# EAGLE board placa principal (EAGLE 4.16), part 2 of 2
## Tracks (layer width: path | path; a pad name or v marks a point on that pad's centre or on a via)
A0
  Bottom 0.305: 18-A0.1 45.71,10.27 arc45 45.34,11.17 39.1,17.41 arc-45 38.73,18.31 38.73,22.23 33.84,38.13 arc73 U2.2 RN3.2
A1
  Top 0.305: U2.17 37.99,33.66 arc-45 37.09,34.03 36.56,34.55 arc45 35.66,34.92 32.27,34.92 arc-45 31.37,35.3 RN3.3
  Bottom 0.305: 17-A1.1 44.82,3.44 arc-45 44.45,4.34 44.45,10.27 arc45 44.07,11.17 38.47,16.77 arc-45 38.09,17.67 38.09,21.91 34.25,34.04 arc72 33.04,34.92 32.27,34.92 arc-45 31.37,35.3 RN3.3
A1''
  Top 0.305: U8.4 131.55,48.26 arc-45 132.45,47.89 133.34,46.99 139.06,46.99 139.32,47.25 arc-45 140.22,47.62 144.78,47.62 X1.23
A2
  Bottom 0.305: 16-A2.1 43.17,10.27 arc45 42.8,11.17 37.83,16.14 arc-45 37.46,17.04 37.46,21.27 33.84,33.05 arc73 U2.4 RN3.4
A3
  Top 0.305: U2.15 37.99,28.57 arc-45 37.09,28.95 36.56,29.47 arc45 35.66,29.84 32.27,29.84 arc-45 31.37,30.22 RN3.5
  Bottom 0.305: 15-A3.1 42.28,3.44 arc-45 41.9,4.34 41.9,10.27 arc45 41.53,11.17 37.2,15.5 arc-45 36.82,16.4 36.82,20.45 arc17 36.77,20.82 34.24,28.95 arc73 33.03,29.84 32.27,29.84 arc-45 31.37,30.22 RN3.5
A4
  Bottom 0.305: 14-A4.1 40.63,10.27 arc45 40.26,11.17 36.56,14.87 arc-45 36.19,15.77 36.19,20.13 arc17 36.13,20.5 33.65,28.57 U2.6 RN3.6
A5
  Top 0.305: RN3.7 31.37,25.14 arc45 32.27,24.77 35.66,24.77 arc-45 36.56,24.39 37.09,23.87 arc45 37.99,23.5 U2.13
  Bottom 0.305: 13-A5.1 39.74,3.44 arc-45 39.36,4.34 39.36,10.27 arc45 38.99,11.17 35.93,14.23 arc-45 35.55,15.13 35.55,19.8 arc18 35.49,20.2 34.26,23.9 arc72 33.05,24.77 32.27,24.77 arc-45 31.37,25.14 RN3.7
A6
  Bottom 0.305: 12-A6.1 38.09,10.27 arc45 37.72,11.17 35.29,13.6 arc-45 34.92,14.5 34.92,19.18 arc17 34.86,19.55 33.84,22.89 arc73 U2.8 RN3.8
A7
  Top 0.305: U2.11 37.99,18.41 arc-45 37.09,18.79 36.56,19.31 arc45 35.66,19.68 32.27,19.68 arc-45 31.37,20.06 RN3.9
  Bottom 0.305: 11-A7.1 37.2,3.44 arc-45 36.82,4.34 36.82,10.27 arc45 36.45,11.17 32.12,15.5 arc-45 31.75,16.4 31.75,19.16 arc45 31.37,20.06 RN3.9
A8
  Bottom 0.305: 10-A8.1 35.55,9.63 arc45 35.18,10.53 30.21,15.5 arc45 29.31,15.88 26.56,15.88 arc-45 25.66,16.25 23.86,18.04 arc-45 23.49,18.94 23.49,22.03 arc17 23.43,22.41 18.41,38.73 U1.2 RN1.2
A9
  Top 0.305: RN1.3 16.13,35.3 arc45 17.03,34.92 19.79,34.92 arc-45 20.69,34.55 21.21,34.03 arc45 22.11,33.66 U1.17
  Bottom 0.305: RN1.3 16.13,35.3 arc45 17.03,34.92 17.8,34.92 arc-72 19.01,34.04 22.86,21.91 22.86,18.31 arc45 23.23,17.41 25.02,15.61 arc45 25.92,15.24 28.68,15.24 arc-45 29.58,14.87 33.91,10.53 arc-45 34.28,9.63 34.28,4.34 arc45 34.66,3.44 9-A9.1
A10
  Bottom 0.305: 8-A10.1 33.02,9.63 arc45 32.64,10.53 28.94,14.23 arc45 28.04,14.61 25.29,14.61 arc-45 24.39,14.98 22.59,16.77 arc-45 22.22,17.67 22.22,21.27 18.6,33.05 arc73 U1.4 RN1.4
A11
  Top 0.305: RN1.5 16.13,30.22 arc45 17.03,29.84 20.42,29.84 arc-45 21.32,29.47 21.85,28.95 arc45 22.75,28.57 U1.15
  Bottom 0.305: RN1.5 16.13,30.22 arc45 17.03,29.84 17.79,29.84 arc-73 19.01,28.95 21.59,20.64 21.59,17.04 arc45 21.96,16.14 23.75,14.34 arc45 24.65,13.97 27.41,13.97 arc-45 28.31,13.6 31.37,10.53 arc-45 31.75,9.63 31.75,4.34 arc45 32.12,3.44 7-A11.1
A12
  Bottom 0.305: 6-A12.1 30.48,9.63 arc45 30.1,10.53 27.67,12.96 arc45 26.77,13.34 24.02,13.34 arc-45 23.12,13.71 21.32,15.5 arc-45 20.95,16.4 20.95,20.32 18.6,27.97 arc73 U1.6 RN1.6
A13
  Top 0.305: RN1.7 16.13,25.14 arc45 17.03,24.77 19.79,24.77 arc-45 20.69,24.39 21.21,23.87 arc45 22.11,23.5 U1.13
  Bottom 0.305: RN1.7 16.13,25.14 arc45 17.03,24.77 17.81,24.77 arc-72 19.02,23.9 20.32,20 20.32,15.77 arc45 20.69,14.87 22.48,13.07 arc45 23.38,12.7 26.14,12.7 arc-45 27.04,12.33 28.83,10.53 arc-45 29.21,9.63 29.21,4.34 arc45 29.58,3.44 5-A13.1
A14
  Bottom 0.305: 4-A14.1 27.94,9.63 arc45 27.56,10.53 26.4,11.69 arc45 25.5,12.06 22.75,12.06 arc-45 21.85,12.44 20.05,14.23 arc-45 19.68,15.13 19.68,19.37 18.6,22.89 arc73 U1.8 RN1.8
A15
  Top 0.305: RN1.9 16.13,20.06 arc45 17.03,19.68 20.42,19.68 arc-45 21.32,19.31 21.85,18.79 arc45 22.75,18.41 U1.11
  Bottom 0.305: RN1.9 16.13,20.06 arc-45 16.51,19.16 16.51,17.04 arc45 16.88,16.14 21.21,11.8 arc45 22.11,11.43 24.87,11.43 arc-45 25.77,11.06 26.29,10.53 arc-45 26.67,9.63 26.67,4.34 arc45 27.04,3.44 3-A15.1
A'0  (via drill 0.8)
  Top 0.254: 112.39,52.39 131.44,52.39
  Top 0.305: U2.18 RN4.2 | U12.10 111.76,76.2 110.86,75.3 arc-45 109.96,74.93 109.74,74.93 arc45 108.84,74.56 107.68,73.4 arc-45 106.78,73.03 50.69,73.03 arc-45 49.79,73.4 v46.98,76.2 | 131.44,52.39 131.7,52.12 arc-45 132.08,51.23 132.08,50.06 arc45 132.45,49.16 132.97,48.63 arc45 133.87,48.26 U8.11 | v111.12,53.34 arc-45 111.66,53.12 112.39,52.39
  Bottom 0.305: RN4.2 44.07,39.63 arc45 44.45,40.53 44.45,50.91 arc-45 44.82,51.81 45.34,52.33 arc45 45.71,53.23 45.71,63.61 arc-45 46.09,64.51 46.61,65.03 arc45 46.98,65.93 v46.98,76.2 46.98,80.64 | v111.12,53.34 111.38,53.6 arc45 111.76,54.5 111.76,55.99 arc-45 112.13,56.89 112.65,57.41 arc45 113.03,58.31 113.03,74.4 arc45 112.65,75.3 112.13,75.83 arc-45 111.76,76.73 U12.10
  Bottom 1.27: 46.98,80.64 46.98,87.63
A'1  (via drill 0.8)
  Top 0.254: 117.79,49.85 124.77,49.85
  Top 0.305: U2.3 35.98,36.2 arc-45 36.88,35.82 37.4,35.3 arc45 38.3,34.92 41.38,34.92 arc45 42.28,35.3 RN4.3 | 46.98,80.64 46.98,80.01 v45.71,78.74 45.71,76.09 arc45 46.09,75.19 48.52,72.76 arc45 49.42,72.39 107.42,72.39 arc45 108.32,72.76 109.48,73.92 arc-45 110.38,74.3 111.86,74.3 arc45 112.76,74.67 114.3,76.2 U12.9 | 124.77,49.85 125.35,50.43 arc-45 126.25,50.8 U8.3 | v116.84,50.8 117.79,49.85
  Top 1.27: 46.98,80.64 46.98,87.63
  Bottom 0.305: RN4.3 43.07,36.2 arc-45 42.17,36.57 arc-45 41.9,37.2 41.9,50.27 arc-45 42.28,51.17 44.71,53.6 arc45 45.08,54.5 45.08,64.24 arc-45 45.45,65.14 arc45 45.71,65.78 v45.71,78.74 | U12.9 114.3,76.73 arc45 114.67,75.83 115.19,75.3 arc-45 115.56,74.4 115.56,52.6 arc45 115.94,51.7 v116.84,50.8
A'2  (via drill 0.8)
  Top 0.305: U2.16 RN4.4 | U12.8 116.84,76.2 113.4,72.76 arc-45 112.5,72.39 v109.85,72.39 109.59,72.13 arc-45 108.69,71.75 48.15,71.75 arc-45 47.25,72.13 44.82,74.56 arc-45 44.45,75.46 v44.45,76.2
  Bottom 0.305: RN4.4 42.54,33.66 41.64,34.55 arc45 40.74,34.92 40.6,34.92 arc-72 39.39,35.79 39.36,35.88 39.36,49.64 arc-45 39.74,50.54 44.07,54.87 arc45 44.45,55.77 v44.45,76.2 44.45,81.28 | U10.1 100.7,56.78 arc-45 100.33,57.68 100.33,62.34 arc-45 100.7,63.24 v109.85,72.39
  Bottom 1.27: 44.45,80.64 44.45,81.28 44.45,87.63
A'3  (via drill 0.8)
  Top 0.305: RN4.5 41.9,29.84 37.99,29.84 arc-45 37.09,30.22 36.56,30.74 arc45 35.66,31.11 U2.5 | 44.45,80.64 44.45,80.01 v43.17,78.74 43.17,75.46 arc45 43.55,74.56 46.61,71.49 arc45 47.51,71.12 113.77,71.12 arc45 114.67,71.49 119.38,76.2 U12.7
  Top 1.27: 44.45,80.64 44.45,87.63
  Bottom 0.305: v43.17,78.74 43.17,56.41 arc-45 42.8,55.51 37.83,50.54 arc45 37.46,49.64 37.46,39.37 39.4,33.27 arc72 40.61,32.38 40.74,32.38 arc-45 41.64,32.01 42.54,31.11 RN4.5 | U9.4 116.63,48.26 arc45 117.52,48.63 117.73,48.84 arc45 118.11,49.74 118.11,74.4 arc-45 118.48,75.3 119,75.83 arc45 119.38,76.73 U12.7
A'4  (via drill 0.8)
  Top 0.305: U2.14 RN4.6 | U12.6 121.92,76.2 116.57,70.86 arc-45 115.67,70.48 46.88,70.48 arc-45 45.98,70.86 42.28,74.56 arc-45 41.9,75.46 v41.9,76.2
  Bottom 0.305: RN4.6 42.54,28.57 41.64,29.47 arc45 40.74,29.84 40.61,29.84 arc-72 39.4,30.73 36.82,38.73 36.82,50.91 arc-45 37.2,51.81 41.53,56.14 arc45 41.9,57.04 v41.9,76.2 41.9,80.64 | U9.5 117.58,45.72 arc45 118.48,46.09 arc45 118.74,46.73 118.74,57.89 arc-45 119.11,58.79 120.65,60.33 120.65,74.4 arc-45 121.02,75.3 121.54,75.83 arc45 121.92,76.73 U12.6
  Bottom 1.27: 41.9,80.64 41.9,87.63
A'5  (via drill 0.8)
  Top 0.254: 112.07,54.29 107.95,54.29
  Top 0.305: RN4.7 42.54,26.04 41.27,24.77 37.99,24.77 arc-45 37.09,25.14 36.56,25.66 arc45 35.66,26.04 U2.7 | 41.9,80.64 41.9,80.01 v40.63,78.74 40.63,75.46 arc45 41.01,74.56 45.34,70.22 arc45 46.24,69.85 117.58,69.85 arc45 118.48,70.22 124.45,76.2 U12.5 | 107.95,54.29 107.37,53.71 arc-45 106.47,53.34 U10.2 | 112.07,54.29 arc-45 112.84,54.61 127.89,54.61 arc45 128.53,54.87 arc45 128.9,55.77 v128.9,55.88
  Top 1.27: 41.9,80.64 41.9,87.63
  Bottom 0.305: v40.63,78.74 40.63,57.68 arc-45 40.26,56.78 36.56,53.08 arc45 36.19,52.18 36.19,38.1 39.4,28.18 arc72 40.61,27.3 40.74,27.3 arc-45 41.64,26.93 42.54,26.04 RN4.7 | U12.5 125.35,75.94 arc-45 125.73,75.04 125.73,60.22 arc45 126.1,59.32 128.9,56.52 v128.9,55.88
A'6  (via drill 0.8)
  Top 0.254: 125.41,49.21 115.56,49.21 | 114.93,49.85 105.72,49.85
  Top 0.305: U2.12 RN4.8 | U12.4 127,76.2 120.38,69.59 arc-45 119.48,69.22 45.61,69.22 arc-45 44.71,69.59 39.74,74.56 arc-45 39.36,75.46 v39.36,76.2 | 105.72,49.85 105.14,50.43 arc45 104.24,50.8 U10.3 | v129.53,49.53 126.17,49.53 arc45 125.41,49.21 | 115.56,49.21 114.93,49.85
  Bottom 0.305: 39.36,80.64 v39.36,76.2 39.36,58.31 arc-45 38.99,57.41 35.93,54.35 arc45 35.55,53.45 35.55,37.15 39.39,25.63 arc72 40.6,24.77 40.74,24.77 arc-45 41.64,24.39 42.54,23.5 RN4.8 | U12.4 127.89,75.94 arc-45 128.27,75.04 128.27,58.95 arc45 128.64,58.05 129.8,56.89 arc-45 130.17,55.99 130.17,55.77 arc-45 129.8,54.87 129.53,54.61 v129.53,49.53
  Bottom 1.27: 39.36,80.64 39.36,87.63
A'7  (via drill 0.8)
  Top 0.305: RN4.9 42.28,20.06 arc-45 41.38,19.68 37.99,19.68 arc-45 37.09,20.06 36.56,20.58 arc45 35.66,20.95 U2.9 | 39.36,80.64 39.36,80.01 v38.09,78.74 38.09,75.46 arc45 38.47,74.56 44.07,68.95 arc45 44.97,68.58 121.39,68.58 arc45 122.29,68.95 129.53,76.2 U12.3 | v34.92,55.24 38.2,55.24 arc-45 39.1,54.87 44.07,49.9 arc45 44.97,49.53 77.57,49.53 arc-45 78.47,49.16 86.62,41.01 arc45 87.52,40.64 U11.9
  Top 1.27: 39.36,80.64 39.36,87.63
  Bottom 0.305: RN4.9 42.54,20.95 41.64,21.85 arc45 40.74,22.23 40.6,22.23 arc-72 39.4,23.1 34.98,36.64 arc-18 34.92,37.03 v34.92,55.24 37.72,58.05 arc45 38.09,58.95 v38.09,78.74
A'8  (via drill 0.8)
  Top 0.305: U1.18 RN2.2 | U12.25 127,61.7 arc45 126.62,62.6 121.65,67.57 arc45 120.75,67.94 44.34,67.94 arc-45 43.44,68.32 37.2,74.56 arc-45 36.82,75.46 v36.82,76.2 | v33.65,56.52 38.2,56.52 arc-45 39.1,56.14 44.71,50.54 arc45 45.61,50.16 77.89,50.16 arc-45 78.79,49.79 85.03,43.55 arc45 85.93,43.18 U11.8
  Bottom 0.305: RN2.2 28.83,39.63 arc45 29.21,40.53 29.21,51.54 arc-45 29.58,52.44 v33.65,56.52 36.45,59.32 arc45 36.82,60.22 v36.82,76.2 36.82,80.64
  Bottom 1.27: 36.82,80.64 36.82,87.63
A'9  (via drill 0.8)
  Top 0.305: RN2.3 27.04,35.3 arc-45 26.14,34.92 22.11,34.92 arc-45 21.21,35.3 20.69,35.82 arc45 19.79,36.2 U1.3 | 36.82,80.64 36.82,80.01 v35.55,78.74 35.55,75.46 arc45 35.93,74.56 42.8,67.68 arc45 43.7,67.31 118.85,67.31 arc-45 119.75,66.94 124.08,62.6 arc-45 124.45,61.7 U12.24 | v118.11,43.18 117.21,42.28 arc-45 116.31,41.91 113.55,41.91 arc45 112.65,41.54 110.48,39.37 107.2,39.37 arc-45 106.3,39.74 103.24,42.81 arc45 102.34,43.18 U10.6
  Top 1.27: 36.82,80.64 36.82,87.63
  Bottom 0.305: RN2.3 27.04,37.09 arc-45 26.67,37.99 26.67,50.91 arc-45 27.04,51.81 35.18,59.95 arc45 35.55,60.85 v35.55,78.74 | U12.24 124.45,60.96 119.75,56.25 arc45 119.38,55.35 119.38,44.98 arc-45 119,44.08 v118.11,43.18
A'10  (via drill 0.8)
  Top 0.305: U1.16 RN2.4 | v116.84,64.14 114.67,66.3 arc45 113.77,66.67 43.07,66.67 arc-45 42.17,67.05 34.66,74.56 arc-45 34.28,75.46 v34.28,76.2 | U11.7 88.79,45.72 arc-45 87.89,46.09 87.36,46.62 arc45 86.46,46.99 84.34,46.99 arc-45 83.44,47.36 79.74,51.06 arc45 78.84,51.44 66.56,51.44 arc-45 65.66,51.81 63.87,53.6 arc45 62.97,53.98 43.07,53.98 arc-45 42.17,54.35 39.1,57.41 arc45 38.2,57.78 v31.11,57.78
  Bottom 0.305: RN2.4 27.04,34.55 arc45 26.14,34.92 25.44,34.92 arc-56 24.38,35.49 24.34,35.56 arc-34 24.12,36.26 24.12,50.27 arc-45 24.5,51.17 v31.11,57.78 33.91,60.59 arc45 34.28,61.49 v34.28,76.2 34.28,80.64 | v116.84,64.14 U12.21
  Bottom 1.27: 34.28,80.64 34.28,87.63
A'11  (via drill 0.8)
  Top 0.305: RN2.5 26.67,29.84 22.75,29.84 arc-45 21.85,30.22 21.32,30.74 arc45 20.42,31.11 U1.5 | 34.28,80.64 34.28,80.01 v33.02,78.74 33.02,75.46 arc45 33.39,74.56 41.53,66.41 arc45 42.43,66.04 108.69,66.04 arc-45 109.59,65.67 112.02,63.24 arc45 112.92,62.87 120.91,62.87 arc-45 121.54,62.6 arc-45 121.92,61.7 U12.23 | v30.48,59.05 38.2,59.05 arc-45 39.1,58.68 42.8,54.98 arc45 43.7,54.61 76.3,54.61 arc-45 77.2,54.24 77.73,53.71 arc45 78.63,53.34 79.48,53.34 arc-45 80.38,52.97 84.71,48.63 arc45 85.61,48.26 U11.6
  Top 1.27: 34.28,80.64 34.28,87.63
  Bottom 0.305: RN2.5 27.04,32.01 arc45 26.14,32.38 25.32,32.38 arc-69 24.13,33.21 23.57,34.71 arc-21 23.49,35.16 23.49,51.54 arc-45 23.86,52.44 v30.48,59.05 33.02,61.59 v33.02,78.74
A'12  (via drill 0.8)
  Top 0.254: 100.01,49.21 103.18,49.21
  Top 0.305: U1.14 RN2.6 | v29.84,60.33 38.2,60.33 arc-45 39.1,59.95 43.44,55.62 arc45 44.34,55.24 71.22,55.24 arc45 72.12,55.62 arc-45 72.76,55.88 79.48,55.88 arc-45 80.38,55.51 84.71,51.17 arc45 85.61,50.8 U11.5 89.64,50.8 arc-45 90.54,50.43 93.6,47.36 arc45 94.5,46.99 97.26,46.99 arc45 98.16,47.36 100.01,49.21 | 103.18,49.21 105.03,47.36 arc45 105.93,46.99 122.66,46.99 arc-45 123.56,46.62 125.35,44.82 arc45 126.25,44.45 v130.81,44.45
  Bottom 0.305: RN2.6 27.04,29.47 arc45 26.14,29.84 25.37,29.84 arc-72 24.16,30.72 21.01,40.45 arc-18 20.95,40.84 20.95,50.91 arc-45 21.32,51.81 v29.84,60.33 31.75,62.23 31.75,80.64 | U12.2 132.97,75.94 arc-45 133.34,75.04 133.34,58.16 arc-45 133.08,57.52 arc45 132.71,56.62 132.71,47.62 131.18,46.09 arc45 130.81,45.19 v130.81,44.45
  Bottom 1.27: 31.75,80.64 31.75,87.63
A'13  (via drill 0.8)
  Top 0.254: 110.48,51.75 129.22,51.75
  Top 0.305: RN2.7 26.67,24.77 22.11,24.77 arc-45 21.21,25.14 20.69,25.66 arc45 19.79,26.04 U1.7 | v30.48,78.74 31.75,80.01 31.75,80.64 | v29.21,61.59 38.2,61.59 arc-45 39.1,61.22 44.07,56.25 arc45 44.97,55.88 70.59,55.88 arc45 71.49,56.25 73.28,58.05 arc-45 74.18,58.42 78.84,58.42 arc-45 79.74,58.05 84.08,53.71 arc45 84.98,53.34 U11.4 89.64,53.34 arc-45 90.54,52.97 93.6,49.9 arc45 94.5,49.53 97.26,49.53 arc45 98.16,49.9 99.95,51.7 arc-45 100.85,52.07 110.17,52.07 110.48,51.75 | U5.1 96.25,31.38 arc45 95.35,31.75 91.96,31.75 arc45 91.06,31.38 v90.8,31.11 | 129.22,51.75 129.8,51.17 arc45 130.7,50.8 v130.81,50.8
  Top 1.27: 31.75,80.64 31.75,87.63
  Bottom 0.305: RN2.7 27.04,26.93 arc45 26.14,27.3 25.37,27.3 arc-72 24.16,28.18 20.38,39.81 arc-18 20.32,40.21 20.32,52.18 arc-45 20.69,53.08 v29.21,61.59 30.48,62.87 v30.48,78.74 | v90.8,31.11 90.54,31.38 arc-45 90.17,32.28 90.17,52.18 arc45 89.79,53.08 arc45 89.16,53.34 U11.4 | U12.26 129.53,58.95 arc45 129.91,58.05 130.43,57.52 arc-45 130.81,56.62 v130.81,50.8
A'14  (via drill 0.8)
  Top 0.305: U1.12 RN2.8 | U11.3 88.26,55.88 87.36,54.98 arc-45 86.46,54.61 85.61,54.61 arc-45 84.71,54.98 79.11,60.59 arc45 78.21,60.96 75.45,60.96 arc45 74.55,60.59 70.85,56.89 arc-45 69.95,56.52 45.61,56.52 arc-45 44.71,56.89 39.1,62.49 arc45 38.2,62.87 v28.57,62.87
  Bottom 0.305: RN2.8 27.04,24.39 arc45 26.14,24.77 25.36,24.77 arc-72 24.16,25.64 19.74,39.18 arc-18 19.68,39.57 19.68,53.45 arc-45 20.05,54.35 v28.57,62.87 29.21,63.5 29.21,80.64
  Bottom 1.27: 29.21,80.64 29.21,87.63
A'15  (via drill 0.8)
  Top 0.254: 95.56,30.16 106.99,30.16
  Top 0.305: U1.9 20.42,20.95 arc-45 21.32,20.58 21.85,20.06 arc45 22.75,19.68 26.14,19.68 arc45 27.04,20.06 RN2.9 | 29.21,80.96 29.21,80.01 v27.94,78.74 27.94,75.46 arc45 28.31,74.56 45.34,57.52 arc45 46.24,57.15 69.32,57.15 arc45 70.22,57.52 73.92,61.22 arc-45 74.82,61.59 83.81,61.59 85.35,60.06 arc45 86.25,59.69 86.46,59.69 arc-45 87.36,59.32 87.89,58.79 arc45 88.79,58.42 U11.2 | v92.7,30.48 94.8,30.48 arc-45 95.56,30.16 | 106.99,30.16 107.57,30.74 arc-45 108.47,31.11 U6.1
  Top 1.27: 29.21,80.64 29.21,80.96 29.21,87.63
  Bottom 0.305: RN2.9 27.04,21.85 arc45 26.14,22.23 25.36,22.23 arc-72 24.16,23.1 19.11,38.54 arc-18 19.05,38.94 19.05,54.72 arc-45 19.42,55.62 27.94,64.14 v27.94,78.74 | U11.2 89.79,58.42 arc-45 90.43,58.16 arc-45 90.8,57.26 90.8,34.18 arc45 91.17,33.28 92.33,32.12 arc-45 92.7,31.22 v92.7,30.48
BRESET  (via drill 0.9)
  Bottom 0.305: v73.66,5.08 73.66,5.82 arc45 73.28,6.72 68.95,11.06 arc-45 68.58,11.96 68.58,41.7 arc-45 68.95,42.6 70.11,43.76 arc45 70.48,44.66 70.48,60.43 arc-45 70.85,61.33 74.55,65.03 arc45 74.93,65.93 74.93,80.64
  Bottom 1.27: 74.93,80.64 74.93,87.63
BUSAK  (via drill 0.8 pad 1.27)
  Bottom 0.305: v71.12,5.08 71.12,5.82 arc45 70.74,6.72 67.68,9.79 arc-45 67.31,10.69 67.31,42.34 arc-45 67.68,43.23 68.84,44.4 arc45 69.21,45.29 69.21,61.7 arc-45 69.58,62.6 72.01,65.03 arc45 72.39,65.93 72.39,80.64
  Bottom 1.27: 72.39,80.64 72.39,87.63
BUSRQ  (via drill 0.8, 0.8 pad 1.27)
  Top 0.305: v71.12,78.74 72.39,80.01 72.39,80.64
  Top 1.27: 72.39,80.64 72.39,87.63
  Bottom 0.305: v71.12,2.54 70.22,3.44 arc-45 69.84,4.34 69.84,5.82 arc45 69.47,6.72 67.04,9.15 arc-45 66.67,10.05 66.67,47.25 arc-45 66.93,47.89 arc45 67.31,48.79 67.31,61.07 arc-45 67.68,61.97 70.74,65.03 arc45 71.12,65.93 v71.12,78.74
CLK4  (via drill 0.8 pad 1.27)
  Bottom 0.305: v86.36,5.08 86.36,6.35 85.46,7.25 arc-45 85.09,8.15 85.09,12.81 arc-45 85.46,13.71 89.79,18.04 arc45 90.17,18.94 90.17,22.23 86.99,25.4 86.99,42.65 arc45 86.62,43.55 85.46,44.71 arc-45 85.09,45.61 85.09,71.86 arc-45 85.46,72.76 86.62,73.92 arc45 86.99,74.82 86.99,78.21 arc-45 87.36,79.11 arc45 87.62,79.75 87.62,80.64
  Bottom 1.27: 87.62,80.64 87.62,87.63
CURSOR  (via drill 0.8 pad 1.27)
  Bottom 0.305: v81.28,5.08 81.28,15.98 arc-45 81.65,16.88 arc45 81.91,17.52 81.91,33.92 arc45 81.65,34.55 arc45 80.75,34.92 79.37,34.92 79.11,35.19 arc-45 78.73,36.09 78.73,43.92 arc45 78.36,44.82 77.84,45.35 arc-45 77.47,46.25 77.47,47.73 arc-45 77.84,48.63 80.27,51.06 arc45 80.64,51.96 80.64,62.97 arc-45 81.01,63.87 arc45 81.28,64.51 81.28,76.31 arc-45 81.65,77.21 82.17,77.73 arc45 82.55,78.63 82.55,80.64
  Bottom 1.27: 82.55,80.64 82.55,87.63
D0
  Top 0.305: U3.2 RN5.2
  Bottom 0.305: 26-D0.1 55.88,13.44 arc45 55.5,14.34 53.71,16.14 arc-45 53.34,17.04 53.34,22.23 49.05,38.12 arc75 U3.2
D0*
  Top 0.305: 109.53,28.57 U6.2 U5.19
D1
  Top 0.305: U3.3 RN5.3
  Bottom 0.305: 25-D1.1 54.98,3.44 arc-45 54.6,4.34 54.6,13.44 arc45 54.23,14.34 53.07,15.5 arc-45 52.7,16.4 52.7,21.91 49.05,35.58 arc75 U3.3
D1*
  Top 0.305: U5.2 99.16,28.57 arc-45 100.06,28.2 100.96,27.3 106.78,27.3 arc-45 107.68,26.93 108.58,26.04 U6.3
D2
  Top 0.305: U3.4 RN5.4
  Bottom 0.305: 24-D2.1 53.34,13.44 arc45 52.96,14.34 52.44,14.87 arc-45 52.06,15.77 52.06,21.59 49.05,33.04 arc75 U3.4
D2*  (via drill 0.8)
  Top 0.305: v95.25,27.3 98.53,27.3 arc-45 99.43,26.93 101.59,24.77 104.77,24.77 106.04,23.5 U6.4
  Bottom 0.305: U5.5 96.41,20.95 arc-45 95.51,21.33 94.98,21.85 arc-45 94.61,22.75 94.61,26.67 v95.25,27.3
D3
  Top 0.305: U3.5 RN5.5
  Bottom 0.305: 23-D3.1 52.44,3.44 arc-45 52.06,4.34 52.06,13.44 arc45 51.69,14.34 arc-45 51.43,14.98 51.43,21.11 arc14 51.39,21.43 49.05,30.5 arc76 U3.5
D3*
  Top 0.305: U5.16 U6.5
D4
  Top 0.305: U3.6 RN5.6
  Bottom 0.305: 22-D4.1 50.79,20.8 arc14 50.76,21.11 49.04,27.96 arc76 U3.6
D4*
  Top 0.305: 109.53,18.41 U6.6 U5.15
D5
  Top 0.305: U3.7 48.25,26.35 47.94,26.04 RN5.7
  Bottom 0.305: 21-D5.1 49.9,3.44 arc-45 49.52,4.34 49.52,6.35 49.79,6.61 arc45 50.16,7.51 50.16,20.49 arc13 50.13,20.78 49.03,25.42 arc77 U3.7
D5*
  Top 0.305: U5.6 99.16,18.41 arc-45 100.06,18.04 100.59,17.52 arc45 101.49,17.14 107.42,17.14 arc-45 108.32,16.77 U6.7
D6
  Top 0.305: U3.8 48.25,23.18 47.94,23.5 RN5.8
  Bottom 0.305: 20-D6.1 48.25,6.35 49.15,7.25 arc45 49.52,8.15 49.52,20.19 arc11 49.5,20.44 49.02,22.87 arc79 U3.8
D6*
  Top 0.305: U5.9 99.16,10.79 arc45 100.06,11.17 100.59,11.69 arc-45 101.49,12.06 106.15,12.06 arc45 107.05,12.44 107.57,12.96 arc-45 108.47,13.34 U6.8
D7
  Top 0.305: RN5.9 U3.9
  Bottom 0.406: 19-D7.1 46.98,3.81 46.98,18.52 arc45 46.61,19.42 46.09,19.95 arc-45 45.71,20.85 RN5.9
D7*
  Top 0.305: U5.12 U6.9
D'0  (via drill 0.8)
  Top 0.254: 113.34,26.99 120.96,26.99 arc-45 121.73,27.3 128.9,27.3 | 108.26,25.08 111.44,25.08
  Top 0.305: U3.18 RN6.2 | U12.11 109.22,76.57 arc-45 108.95,75.94 arc-45 108.05,75.56 102.6,75.56 arc45 101.97,75.3 arc-45 101.07,74.93 58.31,74.93 arc-45 57.41,75.3 57.14,75.56 v57.14,76.2 | U7.9 128.37,13.34 arc45 129.27,13.71 129.53,13.97 129.53,26.14 arc45 129.16,27.04 128.9,27.3 | 111.44,25.08 113.34,26.99 | U5.18 106.78,26.04 arc-45 107.68,25.66 108.26,25.08
  Bottom 0.305: U3.18 arc-76 55.09,36.81 54.6,38.73 54.6,49 arc-45 54.98,49.9 56.77,51.7 arc45 57.14,52.6 v57.14,76.2 57.14,80.64 | U5.18 104.77,26.04 105.03,26.3 arc45 105.41,27.2 105.41,31.86 arc45 105.03,32.76 104.51,33.28 arc-45 104.14,34.18 104.14,57.26 arc45 103.76,58.16 103.24,58.68 arc-45 102.87,59.58 102.87,62.97 arc-45 103.24,63.87 110.75,71.38 arc45 111.12,72.28 111.12,73.77 arc45 110.75,74.67 109.59,75.83 arc-45 109.22,76.73 U12.11
  Bottom 1.27: 57.14,80.64 57.14,87.63
D'1  (via drill 0.8)
  Top 0.254: 79.69,27.62 85.72,27.62 | 102.87,20 113.03,20
  Top 0.305: U3.17 RN6.3 58.52,36.2 arc-45 59.42,35.82 60.58,34.66 arc-45 60.95,33.76 60.95,33.55 arc45 61.33,32.65 63.76,30.22 arc45 64.66,29.84 76.94,29.84 arc-45 77.84,29.47 79.69,27.62 | 57.14,80.64 57.14,80.01 v55.88,78.74 55.88,76.09 arc45 56.25,75.19 56.77,74.67 arc45 57.67,74.3 101.86,74.3 arc45 102.49,74.56 arc-45 103.39,74.93 105.51,74.93 arc-45 106.41,74.56 v106.68,74.3 | 85.72,27.62 arc45 86.49,27.3 92.18,27.3 arc-45 93.08,26.93 93.6,26.41 arc45 94.5,26.04 U5.3 96.83,26.04 102.87,20 | U7.8 127.1,15.88 arc45 128,16.25 arc45 128.27,16.88 128.27,18.52 arc45 127.89,19.42 arc45 127.26,19.68 113.79,19.68 arc-45 113.03,20
  Top 1.27: 57.14,80.64 57.14,87.63
  Bottom 0.305: U3.17 arc-73 55.05,34.26 53.97,37.78 53.97,49.64 arc-45 54.34,50.54 55.5,51.7 arc45 55.88,52.6 v55.88,78.74 | v106.68,74.3 U12.12
D'2  (via drill 0.8)
  Top 0.254: 71.75,20 77.15,20 | 77.78,19.37 82.55,19.37 | 101.91,19.37 110.48,19.37
  Top 0.305: U3.16 RN6.4 69.47,22.6 arc45 70.37,22.23 71.75,22.23 71.75,20 | v104.14,73.98 103.82,73.66 57.04,73.66 arc-45 56.14,74.03 54.98,75.19 arc-45 54.6,76.09 v54.6,76.2 | 77.15,20 77.78,19.37 | 82.55,19.37 arc-45 83.31,19.68 92.18,19.68 arc45 93.08,20.06 U5.4 97.79,23.5 101.91,19.37 | U7.7 125.73,17.14 113.23,17.14 arc-45 112.34,17.52 110.48,19.37
  Bottom 0.305: U3.16 arc-73 55.06,31.72 53.34,37.47 53.34,50.27 arc-45 53.71,51.17 54.23,51.7 arc45 54.6,52.6 v54.6,76.2 54.6,80.64 | v104.14,73.98 U12.13
  Bottom 1.27: 54.6,80.64 54.6,87.63
D'3  (via drill 0.8)
  Top 0.305: U3.15 RN6.5 | v53.34,78.74 54.6,80.01 54.6,80.64 | U12.15 101.59,61.7 arc45 101.22,62.6 arc45 100.59,62.87 57.67,62.87 arc45 56.77,62.49 v53.34,59.05 | U5.17 104.24,23.5 arc-45 105.14,23.12 105.67,22.6 arc45 106.57,22.23 125.2,22.23 arc-45 126.1,21.85 U7.6
  Top 1.27: 54.6,80.64 54.6,87.63
  Bottom 0.305: U3.15 arc-74 55.07,29.18 52.75,37.29 arc-16 52.7,37.64 52.7,51.06 arc-45 52.96,51.7 arc45 53.34,52.6 v53.34,59.05 v53.34,78.74 | U5.17 104.03,23.5 arc-45 103.13,23.87 arc-45 102.87,24.5 102.87,32.49 arc-45 103.24,33.39 arc45 103.5,34.03 103.5,56.62 arc45 103.13,57.52 101.97,58.68 arc-45 101.59,59.58 U12.15
D'4  (via drill 0.8)
  Top 0.305: U3.14 RN6.6 | v52.06,60.33 54.87,63.13 arc-45 55.77,63.5 102.34,63.5 arc-45 103.24,63.13 103.76,62.6 arc-45 104.14,61.7 U12.16 | U7.5 127.89,23.5 arc-45 128.53,23.23 arc-45 128.9,22.33 128.9,15.88 arc-90 127.63,14.61 107.95,14.61 107.05,15.5 arc45 106.15,15.88 U5.14
  Bottom 0.305: U3.14 arc-75 55.07,26.65 51.43,40.01 51.43,51.06 arc-45 51.69,51.7 arc45 52.06,52.6 v52.06,60.33 52.06,80.64 | U5.14 104.77,15.88 105.03,16.14 arc45 105.41,17.04 105.41,24.87 arc-45 105.78,25.77 arc45 106.04,26.41 106.04,56.62 arc45 105.67,57.52 104.51,58.68 arc-45 104.14,59.58 U12.16
  Bottom 1.27: 52.06,80.64 52.06,87.63
D'5  (via drill 0.8)
  Top 0.254: 107.31,24.45 112.07,24.45
  Top 0.305: U3.13 RN6.7 | 52.06,80.64 52.06,80.01 v50.79,78.74 | v50.79,61.59 52.96,63.76 arc-45 53.86,64.14 104.24,64.14 arc-45 105.14,63.76 106.3,62.6 arc-45 106.68,61.7 U12.17 | v102.23,15.88 U5.7 | v106.68,24.77 106.99,24.77 107.31,24.45 | 112.07,24.45 112.39,24.77 125.2,24.77 arc45 126.1,25.14 U7.4
  Top 1.27: 52.06,80.64 52.06,87.63
  Bottom 0.305: U3.13 arc-75 55.07,24.11 50.79,40.01 v50.79,61.59 v50.79,78.74 | U12.17 v106.68,24.77 106.68,16.4 arc-45 106.3,15.5 105.78,14.98 arc-45 104.88,14.61 103.39,14.61 arc-45 102.49,14.98 arc-45 102.23,15.61 v102.23,15.88
D'6  (via drill 0.8)
  Top 0.254: 112.07,27.62 120.33,27.62
  Top 0.305: U3.12 RN6.8 | v49.52,62.87 51.06,64.4 arc-45 51.96,64.77 106.15,64.77 arc-45 107.05,64.4 108.84,62.6 arc-45 109.22,61.7 U12.18 | v106.68,13.97 106.41,14.23 arc45 105.51,14.61 101.49,14.61 arc45 100.59,14.23 100.06,13.71 arc-45 99.16,13.34 U5.8 | 120.33,27.62 120.91,28.2 arc-45 121.81,28.57 U7.3 | v111.12,27.3 111.31,27.3 arc45 112.07,27.62
  Bottom 0.305: U3.12 55.61,20.95 arc-45 54.98,21.22 arc-45 54.6,22.12 54.6,23.01 arc15 54.56,23.34 50.16,39.69 50.16,50.91 arc45 49.79,51.81 49.52,52.07 v49.52,62.87 49.52,80.64 | U12.18 109.22,60.33 107.68,58.79 arc45 107.31,57.89 107.31,28.47 arc45 107.68,27.57 107.95,27.3 | 107.95,27.3 v111.12,27.3 | 107.95,27.3 107.95,15.77 arc-45 107.57,14.87 v106.68,13.97
  Bottom 1.27: 49.52,80.64 49.52,87.63
D'7  (via drill 0.8)
  Top 0.305: U3.11 RN6.9 | 49.52,80.64 49.52,80.01 v48.25,78.74 | v48.25,64.14 49.15,65.03 arc-45 50.05,65.41 108.05,65.41 arc-45 108.95,65.03 111.38,62.6 arc-45 111.76,61.7 U12.19 | U7.2 126.36,31.11 125.73,30.48 118.63,30.48 arc45 117.73,30.11 117.47,29.84 112.92,29.84 arc45 112.02,29.47 v111.76,29.21
  Top 1.27: 49.52,80.64 49.52,87.63
  Bottom 0.305: U3.11 55.13,18.41 arc-45 54.23,18.79 arc-45 53.97,19.42 53.97,22.54 49.52,39.37 49.52,49.64 arc45 49.15,50.54 48.63,51.06 arc-45 48.25,51.96 v48.25,64.14 v48.25,78.74 | U5.13 105.03,12.44 arc45 105.93,12.06 111.38,12.06 arc45 112.02,12.33 arc45 112.39,13.23 112.39,28.57 v111.76,29.21 110.86,30.11 arc-45 110.48,31.01 110.48,33.76 arc45 110.11,34.66 108.32,36.46 arc-45 107.95,37.36 107.95,55.99 arc-45 108.32,56.89 111.76,60.33 U12.19
DIR  (via drill 0.8)
  Top 0.305: v121.92,32.38 125.09,32.38 126.36,33.66 U7.1
  Bottom 0.305: v121.92,32.38 U9.8 | 128.27,45.72 128.27,54.08 arc45 127.89,54.98 U8.1 | 128.27,45.72 U8.5 | U7.1 127.89,34.55 arc45 128.27,35.45 128.27,45.72
DIR'
  Top 0.305: U8.2 132.18,53.34 arc-45 133.08,52.97 arc-45 133.34,52.33 133.34,50.16 133.98,49.53 141.92,49.53 142.24,49.21 X1.11
EXP  (via drill 0.8 pad 1.27)
  Bottom 0.305: v83.81,5.08 83.81,12.81 arc-45 84.19,13.71 87.25,16.77 arc45 87.62,17.67 87.62,22.23 86.36,23.5 86.36,42.34 arc45 85.98,43.23 84.82,44.4 arc-45 84.45,45.29 84.45,72.5 arc-45 84.82,73.4 85.98,74.56 arc45 86.36,75.46 86.36,77.58 arc45 85.98,78.48 85.46,79 arc-45 85.09,79.9 85.09,80.64
  Bottom 1.27: 85.09,80.64 85.09,87.63
GND  (via drill 0.8)
  Top 0.305: RN1.10 14.6,18.41 13.62,19.39 arc-45 13.33,20.1 13.33,39.37 13.67,39.71 arc-45 14.38,40.01 15.98,40.01 arc45 16.88,40.38 U1.1 19.79,41.27 arc-45 20.69,40.9 22.48,39.11 arc45 23.38,38.73 U1.19 | U2.19 38.62,38.73 arc-45 37.72,39.11 35.93,40.9 arc45 35.03,41.27 U2.1 32.12,40.38 arc-45 31.22,40.01 29.97,40.01 arc45 29.21,39.69 29.21,19.68 RN3.10 | U4.1 75.03,41.27 arc-45 75.93,40.9 77.73,39.11 arc45 78.63,38.73 U4.19
  Top 0.61: 15.23,15.88 RN1.10 | 17.78,15.88 U1.10 | 27.94,15.88 RN2.10 | 30.48,15.88 RN3.10 | 33.02,15.88 U2.10 | 43.17,15.88 RN4.10 | 48.25,15.88 U3.10 | 70.48,15.88 RN7.10 | 73.02,15.88 U4.10 | 83.18,15.88 RN8.10 | 91.44,3.17 91.44,2.54 49-GND.1 | 96.52,5.71 U5.10 | 127,8.89 123.19,8.89 120.01,5.71 RN10.1 | 127,8.89 135.36,8.89 arc45 136.26,9.26 136.78,9.79 arc45 137.16,10.69 RN11.10 | 127,8.89 U7.10 | 45.71,15.88 RN5.10 | 58.41,15.88 RN6.10 | U11.10 C5.2 88.9,35.24 89.21,35.24 | 89.21,35.24 93.34,35.24 v93.34,36.2 | 89.21,35.24 89.53,35.56 | v95.25,36.2 95.25,35.88 101.59,35.88 U10.8 | 114.3,35.56 v114.3,36.2 | 127,38.1 U8.7 | 93.98,5.71 C11.2 | 101.59,5.71 D4.P$3
  Top 1.27: 117.63,35.72 117.47,35.88 C9.2 | 117.63,35.72 | 136.84,38.1 137.16,38.1 C7.2 | 109.22,7.3 U6.10
  Top 1.676: 15.23,15.88 17.78,15.88 25.39,15.88 | 25.39,15.88 27.94,15.88 30.48,15.88 33.02,15.88 43.17,15.88 45.71,15.88 48.25,15.88 58.41,15.88 70.48,15.88 73.02,15.88 83.18,15.88 RN9.1 91.44,5.71 | 91.44,5.71 91.44,3.17 | 91.44,5.71 93.98,5.71 96.52,5.71 101.59,5.71 106.68,5.71 108.26,7.3 109.22,7.3 113.34,7.3 114.93,5.71 RN10.1 | 2-GND.1 25.39,15.88 | U12.14 87.94,76.83 87.94,87.63 | 89.53,35.56 114.3,35.56 117.47,35.56 117.63,35.72 120.01,38.1 127,38.1 136.84,38.1
  Bottom 0.305: U3.10 48.25,18.52 arc45 47.88,19.42 47.36,19.95 arc-45 46.98,20.85 46.98,43.92 arc45 46.61,44.82 C3.2 | RN6.10 57.52,19.31 arc-45 57.14,20.21 57.14,36.94 arc45 56.77,37.84 U3.19 | U4.10 72.12,19.31 arc-45 71.75,20.21 71.75,39.48 arc-45 72.12,40.38 U4.1 C4.2 | R1.1 86.36,45.61 arc45 86.73,44.71 87.25,44.19 arc-45 87.62,43.29 87.62,39.9 arc45 88,39 U11.10 | 147.95,25.68 147.91,25.68 | 147.95,25.68 147.95,28.26 | 147.9,22.91 147.95,22.91 147.95,25.68 | RN10.1 119.48,5.71 arc45 120.38,6.09 arc45 120.65,6.72 120.65,27.41 arc45 120.27,28.31 arc45 119.64,28.57 C6.2 | U1.1 C1.2 | U2.1 C2.2
  Bottom 0.406: 132.08,31.11 U7.19
  Bottom 0.61: v95.25,36.2 94.61,36.2 v93.34,36.2 | v114.3,36.2 U9.7 | U5.10 97.79,8.26 | 97.79,8.26 97.79,34.29 U10.8 | U10.8 101.59,35.56 99.69,33.66 99.69,8.26 99.37,8.26 | 97.79,8.26 99.37,8.26 | 99.37,8.26 99.37,33.97 101.28,35.88 101.28,37.15 98.1,33.97 98.1,8.57 98.42,8.57 98.42,33.66 100.96,36.2 100.96,35.88 99.06,33.97 99.06,8.57 | C8.2 99.95,52.44 arc-45 100.33,51.54 100.33,39.9 arc45 100.7,39 U10.8 | 139.69,43.5 140.01,43.5 140.01,43.61 X1.9
  Bottom 0.813: X1.24 147.91,50.52 147.95,50.48 | X1.14 147.9,22.91 147.95,22.86 | X1.15 147.91,25.68 147.95,25.72 | X1.16 147.76,28.45 147.95,28.26 | 127,10.48 127,8.89 132.08,8.89 | RN11.10 135.95,9.35 arc-50 134.97,8.89 132.08,8.89 | 132.08,8.89 2.1
  Bottom 1.27: X1.13 141.97,54.66 141.92,54.61 139.69,54.61 | 139.69,50.8 C10.2 | 100.27,76.46 arc-45 101.17,76.83 U12.14 100.53,76.83 arc45 99.64,76.46 94.35,71.17 arc45 93.98,70.28 93.98,36.2 94.61,36.2 94.61,70.28 arc-45 94.98,71.17 100.27,76.46
  Bottom 1.676: U7.10 129.01,10.79 arc45 129.91,11.17 131.7,12.96 arc45 132.08,13.86 132.08,31.11 132.08,34.29 139.34,41.86 arc44 139.69,42.74 139.69,43.5 139.69,50.8 139.69,54.61 139.69,63.5 144.14,63.5 144.14,56.83 142.24,54.93 140.97,54.93 140.97,62.23 140.65,62.55 141.92,62.55 141.92,55.88 143.19,57.15 143.19,62.87 142.87,63.18 | 147.95,15.88 142.24,15.88 142.24,12.06 143.5,12.06 143.5,15.24 144.78,15.24 144.78,12.7 145.73,12.7 145.73,15.24 147,15.24 147,12.38
  Bottom 1.778: RN11.10 138.22,10.79 arc45 139.11,11.17 139.32,11.38 arc-45 140.22,11.75 147.95,11.75 147.95,15.88 147.95,22.86 147.95,50.48
HALT  (via drill 0.8 pad 1.27)
  Bottom 0.305: v66.04,5.08 66.04,5.82 arc45 65.66,6.72 65.14,7.25 arc-45 64.77,8.15 64.77,49.16 arc-45 65.03,49.79 arc45 65.4,50.69 65.4,62.97 arc-45 65.77,63.87 66.93,65.03 arc45 67.31,65.93 67.31,80.64
  Bottom 1.27: 67.31,80.64 67.31,87.63
INT  (via drill 0.8, 0.8 pad 1.27)
  Top 0.305: v68.58,78.74 69.84,80.01 69.84,80.64
  Top 1.27: 69.84,80.64 69.84,87.63
  Bottom 0.305: v68.58,2.54 67.68,3.44 arc-45 67.31,4.34 67.31,5.82 arc45 66.93,6.72 65.77,7.88 arc-45 65.4,8.78 65.4,48.52 arc-45 65.66,49.16 arc45 66.04,50.06 66.04,62.34 arc-45 66.41,63.24 68.2,65.03 arc45 68.58,65.93 v68.58,78.74
IORQ  (via drill 0.8)
  Top 0.305: 31-IORQ.1 64.39,3.44 arc45 64.77,4.34 64.77,6.46 arc-45 65.14,7.36 70.11,12.33 arc-45 71.01,12.7 74.4,12.7 arc45 75.3,13.07 v76.2,13.97 | RN7.3 70.8,36.2 72.07,34.92 75.67,34.92 arc-45 76.57,34.55 77.09,34.03 arc45 77.99,33.66 U4.17
  Bottom 0.305: v76.2,13.97 77.73,15.5 arc45 78.1,16.4 78.1,23.76 arc-45 78.36,24.39 arc45 78.73,25.29 78.73,28.05 arc-45 79.11,28.95 arc45 79.37,29.58 79.37,32.38 79.37,33.02 80.01,33.66 U4.17
IORQ'  (via drill 0.8)
  Top 0.254: 107.63,54.93 111.44,54.93
  Top 0.305: RN8.3 82.86,36.2 81.96,35.3 arc-45 81.07,34.92 78.63,34.92 arc-45 77.73,35.3 77.2,35.82 arc45 76.3,36.2 U4.3 | 64.77,80.64 64.77,77.47 66.04,76.2 v82.55,76.2 | v81.91,59.69 84.08,57.52 arc45 84.98,57.15 91.54,57.15 arc-45 92.44,56.78 92.97,56.25 arc45 93.87,55.88 U11.18 97.89,55.88 arc-45 98.79,55.51 99.32,54.98 arc45 100.22,54.61 106.86,54.61 arc45 107.63,54.93 | 111.44,54.93 112.02,55.51 arc-45 112.92,55.88 U9.1
  Top 1.27: 64.77,80.64 64.77,87.63
  Bottom 0.305: 82.86,36.2 RN8.3 82.28,37.09 arc-45 81.91,37.99 v81.91,59.69 81.91,74.4 arc-45 82.28,75.3 arc45 82.55,75.94 v82.55,76.2
LPEN  (via drill 0.8, 0.9)
  Top 0.305: v83.81,78.74 85.09,80.01 85.09,80.64
  Top 1.27: 85.09,80.64 85.09,87.63
  Bottom 0.305: v83.81,2.54 82.55,3.81 82.55,12.81 arc-45 82.92,13.71 84.71,15.5 arc45 85.09,16.4 85.09,22.86 85.72,23.5 85.72,42.02 arc45 85.35,42.92 84.19,44.08 arc-45 83.81,44.98 83.81,73.13 arc-45 84.19,74.03 85.35,75.19 arc45 85.72,76.09 85.72,76.94 arc45 85.35,77.84 84.82,78.37 arc45 83.92,78.74 v83.81,78.74
M1  (via drill 0.8)
  Top 0.305: v62.22,78.74 62.22,80.64 | v62.86,52.7 64.39,51.17 arc45 65.29,50.8 78.21,50.8 arc-45 79.11,50.43 84.71,44.82 arc45 85.61,44.45 89,44.45 arc-45 89.9,44.08 95.51,38.47 arc45 96.41,38.1 U11.11
  Top 1.27: 62.22,80.64 62.22,87.63
  Bottom 0.305: 29-M1.1 60.06,3.44 arc-45 59.68,4.34 59.68,5.82 arc-45 60.06,6.72 60.58,7.25 arc45 60.95,8.15 60.95,36.3 arc-45 61.33,37.2 arc45 61.59,37.84 61.59,49.64 arc-45 61.96,50.54 62.49,51.06 arc45 62.86,51.96 v62.86,52.7 62.86,77.58 arc45 62.49,78.48 v62.22,78.74
MREQ  (via drill 0.8)
  Top 0.305: v60.32,38.73 RN7.2 U4.2
  Bottom 0.305: 28-MREQ.1 58.41,5.82 arc-45 58.79,6.72 59.31,7.25 arc45 59.68,8.15 59.68,37.57 arc-45 60.06,38.47 v60.32,38.73
MREQ'  (via drill 0.8)
  Top 0.305: v78.73,46.99 78.47,47.25 arc45 77.57,47.62 65.93,47.62 arc45 65.03,47.25 arc-45 64.39,46.99 v60.32,46.99 | U4.18 RN8.2
  Bottom 0.305: U4.18 80.01,36.2 79.74,36.46 arc-45 79.37,37.36 79.37,45.83 arc45 79,46.73 v78.73,46.99 | v60.32,46.99 60.32,49.64 arc-45 60.69,50.54 61.22,51.06 arc45 61.59,51.96 61.59,76.94 arc45 61.22,77.84 60.06,79 arc-45 59.68,79.9 59.68,80.64
  Bottom 1.27: 59.68,80.64 59.68,87.63
N$1  (via drill 0.8 pad 1.27)
  Top 0.406: v25.39,2.54 12.01,15.92 arc-45 11.42,17.34 11.42,53.46 arc-45 12.01,55.2 26.08,69.26 arc45 26.67,70.36 26.67,80.64
  Top 1.27: 26.67,80.64 26.67,87.63
N$2
  Top 0.305: U9.6 113.55,43.18 arc45 112.65,42.81 112.13,42.28 arc-45 111.23,41.91 107.2,41.91 arc-45 106.3,42.28 103.24,45.35 arc45 102.34,45.72 U10.5
N$3
  Bottom 0.305: U11.1 4.1 R1.2
N$4  (via drill 0.8)
  Top 0.305: v46.98,62.87 52.06,57.78 68.68,57.78 arc45 69.58,58.16 73.28,61.86 arc-45 74.18,62.23 90.27,62.23 arc-45 91.17,61.86 94.24,58.79 arc45 95.14,58.42 U11.19
  Bottom 0.305: U3.1 48.25,49.64 arc45 47.88,50.54 47.36,51.06 arc-45 46.98,51.96 v46.98,62.87
N$5
  Top 0.305: U11.12 96.62,40.64 arc45 97.52,41.01 99.32,42.81 arc45 99.69,43.71 99.69,47.1 arc-45 100.06,48 arc-45 100.7,48.26 U10.4
N$6
  Top 0.305: D2.P$3 88.9,21.06 arc-45 89.27,21.96 arc-45 89.9,22.23 92.18,22.23 arc45 93.08,22.6 arc45 93.34,23.23 93.34,23.6 arc45 92.97,24.5 arc45 92.33,24.77 83.07,24.77 arc-45 82.17,25.14 81.28,26.04 U4.14
N$7
  Top 0.254: 81.91,21.91 85.4,21.91
  Top 0.305: 85.4,21.91 D1.P$3 | U4.12 81.91,21.91
N$8
  Top 0.305: U10.7 102.34,40.64 arc-45 103.24,40.27 106.3,37.2 arc45 107.2,36.83 109.96,36.83 arc45 110.86,37.2 111.38,37.73 arc-45 112.28,38.1 116.31,38.1 arc45 117.21,38.47 120.27,41.54 arc-45 121.17,41.91 131.55,41.91 arc45 132.45,42.28 132.97,42.81 arc-45 133.87,43.18 U8.9
N$9
  Bottom 0.305: U9.3 114.19,50.8 arc45 113.29,50.43 arc45 113.03,49.79 113.03,11.32 arc-45 112.65,10.42 112.13,9.9 arc-45 111.23,9.53 105.93,9.53 arc45 105.03,9.15 U5.11
N$10
  Top 0.305: U8.6 130.91,43.18 arc45 131.81,43.55 132.34,44.08 arc-45 133.24,44.45 137.9,44.45 arc-45 138.8,44.08 140.28,42.6 arc45 141.17,42.23 144.78,42.23 X1.21
N$11
  Top 0.305: U10.9 109.96,38.1 arc45 110.86,38.47 111.38,39 arc-45 112.28,39.37 116.31,39.37 arc45 117.21,39.74 120.27,42.81 arc-45 121.17,43.18 U9.9
  Bottom 0.305: U9.9 121.81,43.18 arc-45 120.91,43.55 arc-45 120.65,44.19 120.65,49.64 arc-45 121.02,50.54 arc-45 121.65,50.8 U9.12
N$12
  Bottom 1.27: 26.67,80.64 26.67,87.63
N$13  (via drill 0.8)
  Top 0.305: U9.11 123.93,48.26 arc-45 124.83,47.89 125.35,47.36 arc45 126.25,46.99 130.91,46.99 arc-45 131.81,46.62 v132.71,45.72
  Bottom 0.305: v132.71,45.72 132.97,45.98 arc45 133.34,46.88 133.34,51.54 arc-45 133.72,52.44 U8.13
N$14
  Top 0.305: U8.8 135.51,41.54 arc-45 136.41,41.91 137.26,41.91 arc-45 138.16,41.54 139.96,39.74 arc45 140.86,39.37 143.19,39.37 arc-45 143.5,38.6 arc45 143.86,37.74 144.78,36.83 X1.19
N$15
  Top 0.305: U8.10 138.53,45.72 arc-45 139.43,45.35 arc45 140.07,45.09 144.78,45.09 X1.22
N$16
  Top 0.305: U8.12 134.72,50.8 arc45 135.62,51.17 136.15,51.7 arc-45 137.05,52.07 142.24,52.07 X1.12
N$17
  Top 0.305: D3.P$3 93.98,10.79 95.25,9.53 113.77,9.53 arc45 114.67,9.9 115.19,10.42 arc-45 116.09,10.79 U6.12
N$18  (via drill 0.8)
  Top 0.305: U6.19 116.94,28.57 arc45 117.84,28.95 118.37,29.47 arc-45 119.27,29.84 v130.17,29.84 | v130.81,63.5 130.81,60.85 arc-45 130.43,59.95 arc-45 129.8,59.69 120.54,59.69 arc-45 119.64,60.06 arc-45 119.38,60.7 U12.22
  Bottom 0.305: v130.17,29.84 129.91,30.11 arc-45 129.53,31.01 129.53,45.19 arc-45 129.91,46.09 132.08,48.26 132.08,56.62 arc45 131.7,57.52 131.18,58.05 arc-45 130.81,58.95 v130.81,63.5
N$19
  Top 0.305: U6.13 RN10.4 SV1.3
N$20
  Top 0.305: U6.14 RN10.5 SV1.5
N$21
  Top 0.305: U6.15 RN10.6 SV1.7
N$22
  Top 0.305: U6.16 RN10.7 SV1.9
N$23
  Top 0.305: U6.17 RN10.8 SV1.11
N$24
  Top 0.305: U6.18 RN10.9 SV1.13
N$25
  Top 0.305: U6.11 RN10.2 119.69,8.26 SV1.1
N$26
  Top 0.305: U7.11 RN11.9 137.9,13.34 arc45 138.8,13.71 139.96,14.87 arc45 140.33,15.77 140.33,20.11 arc-45 140.7,21.01 140.91,21.22 arc-45 141.81,21.59 142.24,21.59 X1.1
N$27
  Top 0.305: U7.12 RN11.8
  Bottom 0.305: X1.2 142.06,24.31 141.92,24.45 140.7,23.23 arc45 140.33,22.33 140.33,18.31 arc-45 139.96,17.41 138.8,16.25 arc-45 137.9,15.88 RN11.8
N$28
  Top 0.305: U7.13 RN11.7 137.26,18.41 arc45 138.16,18.79 138.69,19.31 arc45 139.06,20.21 139.06,20.43 arc-45 139.43,21.33 139.96,21.85 arc45 140.33,22.75 140.33,25.51 arc-45 140.7,26.41 140.91,26.62 arc-45 141.81,26.99 142.24,26.99 X1.3
N$29
  Top 0.305: U7.14 RN11.6
  Bottom 0.305: RN11.6 137.9,20.95 arc45 138.8,21.33 139.01,21.54 arc45 139.38,22.43 139.38,25.19 arc-45 139.75,26.09 140.59,26.93 arc45 140.97,27.83 140.97,29.53 arc-45 141.73,29.84 142.24,29.84 X1.4
N$30
  Top 0.305: U7.15 RN11.5 137.26,23.5 arc45 138.16,23.87 138.69,24.39 arc45 139.06,25.29 139.06,25.51 arc-45 139.43,26.41 139.96,26.93 arc45 140.33,27.83 140.33,31.22 arc-45 140.7,32.12 141.17,32.59 arc-90 142.03,32.59 X1.5
N$31
  Top 0.305: U7.16 RN11.4
  Bottom 0.305: RN11.4 arc45 137.7,26.26 139.64,28.2 arc45 140.01,29.1 140.01,33.45 arc-45 140.38,34.34 141.28,35.24 141.92,35.24 142.01,35.33 X1.6
N$32
  Top 0.305: U7.17 RN11.3 137.26,28.57 arc45 138.16,28.95 138.69,29.47 arc45 139.06,30.37 139.06,31.22 arc-45 139.43,32.12 139.96,32.65 arc45 140.33,33.55 140.33,36.3 arc-45 140.7,37.2 141.6,38.1 X1.7
N$33
  Top 0.305: U7.18 RN11.2
  Bottom 0.305: RN11.2 arc45 137.7,31.34 138.69,32.33 arc45 139.06,33.23 139.06,37.89 arc-45 139.43,38.79 141.14,40.5 arc-45 142.04,40.87 X1.8
N$34
  Top 1.27: 147.95,29.84 147.95,29.95 arc45 147.58,30.85 arc45 146.94,31.11 144.78,31.11 X1.17 X1.18
  Top 1.676: O.1 142.82,10.11 arc-45 143.71,10.48 146.47,10.48 arc45 147.37,10.85 147.58,11.06 arc45 147.95,11.96 147.95,29.84
N$35
  Top 0.305: EX.1 122.81,1.01 arc45 123.71,0.64 130.28,0.64 arc45 131.18,1.01 1.1
  Bottom 0.305: D4.P$4 112.5,2.54 arc45 113.4,2.91 arc-45 114.03,3.17 120.12,3.17 arc-45 121.02,2.8 EX.1
N$36
  Bottom 0.305: T.1 arc45 119.6,1.36 119.95,1.01 arc45 120.85,0.64 127.1,0.64 arc45 128,1.01 131.07,4.07 arc-45 131.97,4.45 134.72,4.45 arc45 135.62,4.82 140.59,9.79 arc-45 141.49,10.16 148.59,10.16 arc90 149.86,11.43 149.86,52.07 arc90 148.59,53.34 144.78,53.34 X1.25
NMI  (via drill 0.9)
  Bottom 0.305: v68.58,5.08 68.58,5.82 arc45 68.2,6.72 66.41,8.52 arc-45 66.04,9.42 66.04,47.89 arc-45 66.3,48.52 arc45 66.67,49.42 66.67,61.7 arc-45 67.04,62.6 69.47,65.03 arc45 69.84,65.93 69.84,80.64
  Bottom 1.27: 69.84,80.64 69.84,87.63
RAMDIS
  Top 0.305: D2.P$4 88.9,10.69 arc-45 88.52,9.79 88,9.26 arc-45 87.1,8.89 83.55,8.89 arc45 82.92,8.63 arc45 82.55,7.73 82.55,4.34 arc-45 82.17,3.44 45-RAMDIS.1
  Bottom 0.305: D2.P$4 89,10.79 arc45 89.9,11.17 92.33,13.6 arc45 92.7,14.5 92.7,19.16 arc45 92.33,20.06 RN9.3
RAMDIS'  (via drill 0.8)
  Top 0.254: 78.42,26.99 85.4,26.99
  Top 0.305: 82.55,80.64 82.55,80.01 v81.28,78.74 | U4.6 v76.83,28.57 78.42,26.99 | 85.4,26.99 85.98,26.41 arc45 86.88,26.04 RN9.5 | U11.14 94.5,45.72 arc-45 93.6,46.09 90.54,49.16 arc45 89.64,49.53 85.61,49.53 arc-45 84.71,49.9 80.38,54.24 arc45 79.48,54.61 v79.37,54.61
  Top 1.27: 82.55,80.64 82.55,87.63
  Bottom 0.305: v81.28,78.74 81.28,78.48 arc-45 81.01,77.84 arc45 80.64,76.94 80.64,65.3 arc-45 80.27,64.4 79.74,63.87 arc45 79.37,62.97 v79.37,54.61 79.37,51.96 arc-45 79,51.06 76.57,48.63 arc45 76.2,47.73 76.2,29.74 arc45 76.57,28.84 v76.83,28.57
RAMRD
  Top 0.254: 76.51,19.37 71.43,19.37
  Top 0.305: U4.11 77.99,18.41 arc-45 77.09,18.79 76.51,19.37 | 71.43,19.37 70.85,19.95 arc-45 70.48,20.85 RN7.9
  Bottom 0.305: 44-RAMRD.1 78.73,7.09 arc-45 79.11,7.99 80.27,9.15 arc45 80.64,10.05 U4.11
RAMRD'  (via drill 0.8)
  Top 0.254: 78.42,20 82.23,20
  Top 0.305: U4.9 76.94,20.95 arc-45 77.84,20.58 78.42,20 | 82.23,20 RN8.9 | U11.16 94.5,50.8 arc-45 93.6,51.17 90.54,54.24 arc45 89.64,54.61 88.79,54.61 arc45 87.89,54.24 arc-45 87.25,53.98 85.29,53.98 arc-45 84.4,54.35 79.43,59.32 arc45 78.53,59.69 v78.1,59.69
  Bottom 0.305: 80.01,80.64 80.01,65.93 arc-45 79.63,65.03 78.47,63.87 arc45 78.1,62.97 v78.1,59.69 78.1,51.96 arc-45 77.73,51.06 75.93,49.27 arc45 75.56,48.37 75.56,23.39 arc-45 75.19,22.49 74.03,21.33 arc-45 73.13,20.95 U4.9
  Bottom 1.27: 80.01,80.64 80.01,87.63
RD  (via drill 0.8)
  Top 0.305: RN7.4 70.8,33.66 | v63.49,33.66 RN7.4 | RN7.4 U4.4
  Bottom 0.305: 32-RD.1 v63.49,33.66
RD'  (via drill 0.8)
  Top 0.305: v93.98,29.21 88.15,29.21 arc-45 87.25,29.58 RN8.4 U4.16 79.26,31.11 arc-45 78.36,31.49 77.84,32.01 arc45 76.94,32.38 63.39,32.38 arc-45 62.49,32.76 arc-45 62.22,33.39 62.22,34.4 arc-45 62.6,35.3 v63.49,36.2 | v98.42,39.37 99.95,40.9 arc45 100.33,41.8 100.33,45.83 arc-45 100.7,46.73 arc-45 101.33,46.99 102.97,46.99 arc-45 103.87,46.62 105.67,44.82 arc45 106.57,44.45 116.94,44.45 arc45 117.84,44.82 118.37,45.35 arc-45 119.27,45.72 U9.10
  Bottom 0.305: U11.17 96.62,53.34 arc-45 97.52,52.97 98.05,52.44 arc-45 98.42,51.54 v98.42,39.37 98.42,36.72 arc-45 98.05,35.82 94.35,32.12 arc45 93.98,31.22 v93.98,29.21 | 64.77,80.64 64.77,51.33 arc-45 64.39,50.43 63.87,49.9 arc45 63.49,49 v63.49,36.2
  Bottom 1.27: 64.77,80.64 64.77,87.63
READY  (via drill 0.8, 0.8 pad 1.27)
  Top 0.305: v73.66,78.74 74.93,80.01 74.93,80.64
  Top 1.27: 74.93,80.64 74.93,87.63
  Bottom 0.305: v73.66,2.54 72.76,3.44 arc-45 72.39,4.34 72.39,5.82 arc45 72.01,6.72 68.31,10.42 arc-45 67.94,11.32 67.94,42.02 arc-45 68.31,42.92 69.47,44.08 arc45 69.84,44.98 69.84,61.07 arc-45 70.22,61.97 73.28,65.03 arc45 73.66,65.93 v73.66,78.74
RFSH  (via drill 0.8 pad 1.27)
  Bottom 0.305: v60.95,5.08 60.95,5.82 arc-45 61.33,6.72 61.85,7.25 arc45 62.22,8.15 62.22,49 arc-45 62.6,49.9 63.76,51.06 arc45 64.13,51.96 64.13,78.21 arc45 63.76,79.11 62.22,80.64
  Bottom 1.27: 62.22,80.64 62.22,87.63
ROMDIS
  Top 0.305: 43-ROMDIS.1 79.63,3.44 arc45 80.01,4.34 80.01,8.36 arc-45 80.38,9.26 81.54,10.42 arc-45 82.44,10.79 D1.P$4
  Bottom 0.305: D1.P$4 86.36,12.81 arc-45 86.73,13.71 RN9.2
ROMDIS'  (via drill 0.8)
  Top 0.254: 77.15,22.54 85.09,22.54
  Top 0.305: 80.01,80.64 80.01,80.01 v78.73,78.74 | U11.13 94.18,43.18 arc-45 93.29,43.55 90.22,46.62 arc45 89.32,46.99 88.63,46.99 arc-45 88,47.25 arc45 87.1,47.62 84.98,47.62 arc-45 84.08,48 79.74,52.33 arc45 78.84,52.7 v76.83,52.7 | 85.09,22.54 85.67,23.12 arc-45 86.56,23.5 RN9.4 | U4.8 75.67,23.5 arc-45 76.57,23.12 77.15,22.54
  Top 1.27: 80.01,80.64 80.01,87.63
  Bottom 0.305: v78.73,78.74 78.73,65.93 arc-45 78.36,65.03 77.2,63.87 arc45 76.83,62.97 v76.83,52.7 76.83,51.96 arc-45 76.46,51.06 75.3,49.9 arc45 74.93,49 74.93,24.77 73.66,23.5 U4.8 | D3.P$4 94.08,8.26 arc45 94.98,8.63 95.25,8.89 95.25,19.79 arc45 94.87,20.69 92.44,23.12 arc45 91.54,23.5 RN9.4
ROMEN
  Top 0.305: RN7.7 71.75,24.77 75.67,24.77 arc-45 76.57,24.39 77.09,23.87 arc45 77.99,23.5 U4.13
  Bottom 0.305: 42-ROMEN.1 76.2,5.82 arc-45 76.57,6.72 79,9.15 arc45 79.37,10.05 79.37,22.33 arc-45 79.74,23.23 arc-45 80.38,23.5 U4.13
ROMEN'  (via drill 0.8)
  Top 0.254: 99.37,49.85 103.82,49.85 | 104.45,49.21 110.17,49.21
  Top 0.305: U4.7 75.67,26.04 arc-45 76.57,25.66 77.09,25.14 arc45 77.99,24.77 80.75,24.77 arc-45 81.65,24.39 82.17,23.87 arc45 83.07,23.5 RN8.8 | v74.29,57.15 79.16,57.15 arc-45 80.06,56.78 84.4,52.44 arc45 85.29,52.07 89.64,52.07 arc-45 90.54,51.7 93.6,48.63 arc45 94.5,48.26 U11.15 97.26,48.26 arc45 98.16,48.63 99.37,49.85 | 103.82,49.85 104.45,49.21 | 110.17,49.21 v111.12,48.26
  Bottom 0.305: U4.7 73.28,26.04 arc45 73.92,26.3 arc45 74.29,27.2 v74.29,57.15 74.29,61.7 arc-45 74.66,62.6 77.09,65.03 arc45 77.47,65.93 77.47,80.64 | v111.12,48.26 111.12,50.27 arc-45 111.49,51.17 112.02,51.7 arc45 112.39,52.6 112.39,55.35 arc-45 112.76,56.25 113.92,57.41 arc45 114.3,58.31 U12.20
  Bottom 1.27: 77.47,80.64 77.47,87.63
RSET  (via drill 0.8, 0.9)
  Top 0.305: v76.2,78.74 77.47,80.01 77.47,80.64
  Top 1.27: 77.47,80.64 77.47,87.63
  Bottom 0.305: v76.2,2.54 75.3,3.44 arc-45 74.93,4.34 74.93,5.82 arc45 74.55,6.72 69.58,11.69 arc-45 69.21,12.59 69.21,41.38 arc-45 69.58,42.28 70.74,43.44 arc45 71.12,44.34 71.12,59.8 arc-45 71.49,60.7 75.82,65.03 arc45 76.2,65.93 v76.2,78.74
VCC  (via drill 0.8)
  Top 0.305: 64.1 86.46,60.96 arc-45 87.36,60.59 87.89,60.06 arc45 88.79,59.69 90.91,59.69 arc-45 91.81,59.32 93.6,57.52 arc45 94.5,57.15 98.53,57.15 arc45 99.43,57.52 100.33,58.42 | U12.28 U12.1 | 27.94,43.81 C2.1 | 40.63,43.81 C3.1 | 67.94,43.81 C4.1 | C6.1 119.06,33.66 119.38,33.34
  Top 0.406: C7.1 137.47,35.56 137.16,35.24 137.16,34.92
  Top 0.61: RN1.1 15.23,43.81 13.33,43.81 12.69,43.81 C1.1 | 25.39,43.81 U1.20 | 27.94,43.81 RN2.1 | 40.63,43.81 U2.20 | 43.17,43.81 RN4.1 | 30.48,43.81 RN3.1 | 55.88,43.81 U3.20 | 70.48,43.81 70.48,43.5 | 70.48,43.5 RN7.1 | 80.64,43.81 U4.20 | 70.48,43.5 70.8,43.81 | 58.41,43.81 RN6.1 | 109.22,58.42 U10.16 | 109.22,58.42 100.33,58.42 | 100.33,58.42 97.79,60.96 U11.20 | U9.14 121.92,58.42 | 121.92,58.42 109.22,58.42 | 121.92,58.42 132.08,58.42 | 132.08,58.42 U12.27 | 134.62,58.42 U12.28 | 132.08,58.42 134.62,58.42 | 134.62,58.42 U8.14 C10.1 | 134.62,35.88 U7.20 | 104.14,33.34 U5.20 | 82.7,42.39 83.34,42.39 83.18,42.23 RN8.1 | 116.84,33.34 U6.20 | 45.71,43.81 RN5.1 | 136.84,35.88 137.16,35.88 C7.1 137.16,34.92 RN11.1 | 88.9,33.34 C5.1 | 100.33,58.42 C8.1
  Top 1.016: 27-VCC.1 58.41,0.95 106.68,0.95 109.8,4.07 arc-45 110.69,4.45 v111.76,4.45 112.18,4.45 arc-45 113.08,4.07 113.34,3.81 v124.77,3.81
  Top 1.27: 59.68,80.33 59.68,87.63 | 59.68,80.33 59.05,79.69 59.05,77.79 59.37,77.47 v59.68,76.83 | v59.68,76.83 59.05,77.15 59.05,76.52 59.68,76.52 | 59.68,76.52 60.32,76.52 60.32,79.69 59.68,80.33 | 59.68,76.52 59.68,80.33 | v59.68,76.83 59.68,76.52
  Top 1.676: 13.33,43.81 25.39,43.81 27.94,43.81 30.48,43.81 40.63,43.81 43.17,43.81 45.71,43.81 55.88,43.81 58.41,43.81 67.94,43.81 70.48,43.81 | 70.8,43.81 80.64,43.81 81.28,43.81 82.7,42.39 86.99,38.1 86.99,33.97 87.62,33.34 88.9,33.34 v101.59,33.34 104.14,33.34 116.84,33.34 119.38,33.34 121.92,35.88 C9.1 134.62,35.88 136.84,35.88
  Bottom 0.61: C11.1 99.16,2.54 arc45 100.06,2.91 100.59,3.44 arc45 100.96,4.34 100.96,32.7 v101.59,33.34
  Bottom 1.016: 27-VCC.1 58.41,0.95 106.15,0.95 arc45 107.05,1.32 109.8,4.07 arc-45 110.69,4.45 v111.76,4.45 | 124.77,4.45 v124.77,3.81
  Bottom 1.27: U3.20 56.83,41.91 56.83,49.32 arc-45 57.2,50.22 58.68,51.7 arc45 59.05,52.6 59.05,76.83 v59.68,76.83 60.32,76.83 60.32,52.6 arc-45 59.95,51.7 58.79,50.54 arc45 58.41,49.64 RN6.1 57.46,41.27 | 57.46,41.27 56.83,41.27 56.51,41.59 57.14,41.59 57.46,41.27 | 57.46,41.27 57.46,49.21 58.1,49.85 | 124.77,6.99 P@.1 | P.1 124.77,1.91 v124.77,3.81
  Bottom 1.422: 124.77,55.88 123.5,55.88 | 123.5,55.88 123.19,55.88 | 123.5,55.88 124.45,54.93 | 123.5,55.88 U9.14
  Bottom 1.676: 124.77,4.13 124.77,4.45 124.77,6.99 | 124.77,6.99 SV1.2 SV1.4 SV1.6 | 124.77,6.99 SV1.8 SV1.10 SV1.12 | SV1.12 124.77,23.81 | SV1.12 SV1.14 124.77,35.88 | 124.77,35.88 124.77,55.88 | C9.1 124.77,35.88
WR  (via drill 0.8)
  Top 0.305: 33-WR.1 66.93,3.44 arc45 67.31,4.34 67.31,7.09 arc-45 67.68,7.99 70.74,11.06 arc-45 71.64,11.43 75.03,11.43 arc45 75.93,11.8 v78.1,13.97
  Bottom 0.305: v78.1,13.97 arc-45 78.32,14.51 78.36,14.55 arc45 78.73,15.45 78.73,22.97 arc-45 79.11,23.87 arc45 79.37,24.5 79.37,27.41 arc-45 79.74,28.31 arc-45 80.38,28.57 U4.15
WR'  (via drill 0.8)
  Top 0.254: 95.88,29.53 107.63,29.53
  Top 0.305: 67.31,80.64 67.31,78.11 67.94,77.47 83.81,77.47 v84.45,76.83 | U4.5 76.94,31.11 arc-45 77.84,30.74 78.36,30.22 arc45 79.26,29.84 81.38,29.84 arc45 82.28,30.22 RN8.5 83.92,31.11 arc-45 84.82,30.74 87.25,28.31 arc45 88.15,27.94 93.77,27.94 arc45 94.66,28.31 95.88,29.53 | U9.2 U9.13 | 107.63,29.53 arc-45 108.39,29.84 109.96,29.84 arc45 110.86,30.22 v111.76,31.11
  Top 1.27: 67.31,80.64 67.31,87.63
  Bottom 0.305: v84.45,76.83 84.45,76.09 arc-45 84.08,75.19 83.55,74.67 arc45 83.18,73.77 83.18,44.66 arc45 83.55,43.76 84.71,42.6 arc-45 85.09,41.7 85.09,32.12 arc-45 84.82,31.49 arc-45 83.92,31.11 RN8.5 | v111.76,31.11 112.02,31.38 arc45 112.39,32.28 112.39,50.27 arc-45 112.76,51.17 arc45 113.03,51.81 113.03,52.18 arc-45 113.4,53.08 arc-45 114.03,53.34 U9.2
